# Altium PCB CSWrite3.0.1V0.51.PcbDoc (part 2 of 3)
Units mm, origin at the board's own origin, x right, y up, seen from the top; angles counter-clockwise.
Board outline 100 x 80 mm, 4 copper layers (Top Layer, power, gnd, Bottom Layer), stack 0.778 mm thick; 246 components, 181 nets, 873 pads, 864 vias.
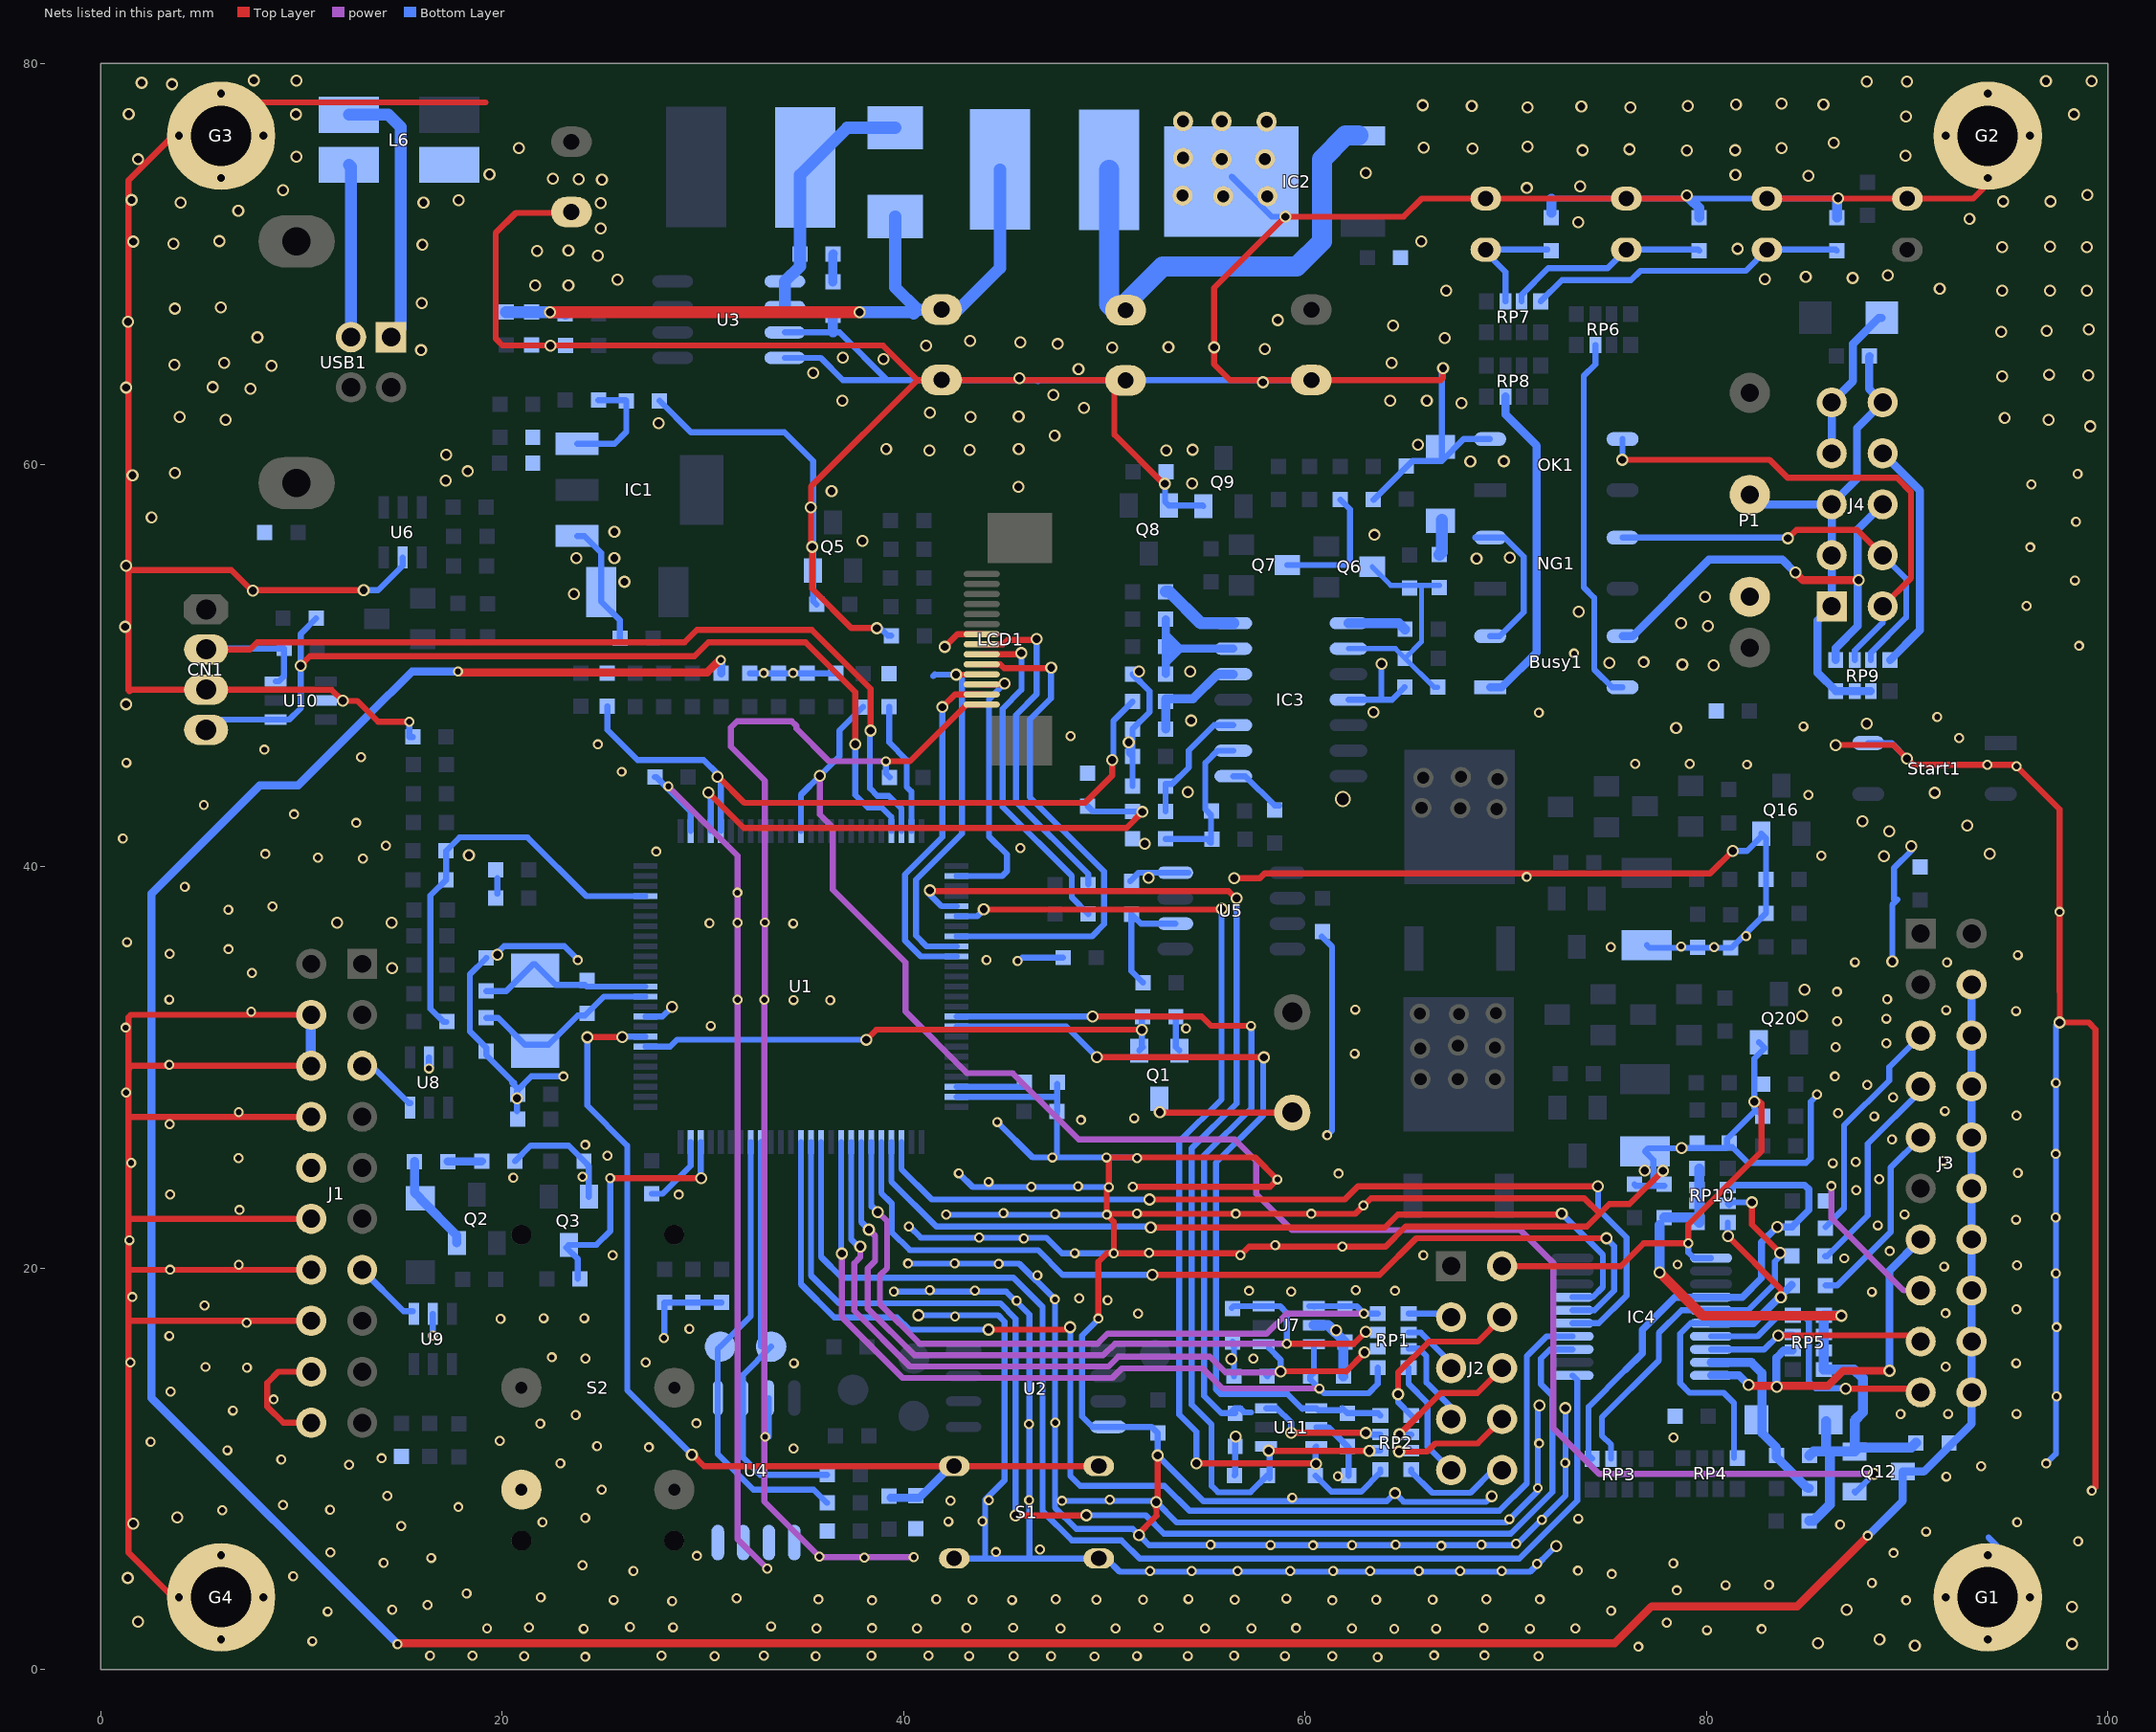
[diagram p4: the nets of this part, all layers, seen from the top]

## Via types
v1: diameter 0.5, hole 0.3, Top Layer to Bottom Layer, 444 vias
v2: diameter 0.6, hole 0.4, Top Layer to Bottom Layer, 412 vias
v3: diameter 0.8, hole 0.6, Top Layer to Bottom Layer, 8 vias

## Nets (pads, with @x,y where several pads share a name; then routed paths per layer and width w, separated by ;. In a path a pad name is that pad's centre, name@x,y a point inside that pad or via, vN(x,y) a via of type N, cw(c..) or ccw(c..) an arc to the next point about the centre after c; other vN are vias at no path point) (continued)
Buzzer: Q1.1 R8.1 U1.7 | length 26.9
  Top Layer w0.3: v2(38.13,31.37) 38.63,31.87 v2(51.87,31.87)
  Bottom Layer w0.3: U1.7@27.137,31.022 28.36,31.022 28.708,31.37 v2(38.13,31.37) v2@38.15,31.37 ; Q1.1@51.734,30.83 51.908,31.005 51.87,31.043 v2(51.87,31.87) 51.87,32.474 R8.1@51.908,32.512
CLK-a: IC4.5 U1.78 | length 46.3
  Top Layer w0.3: v2(52.25,23.41) 61.97,23.41 62.63,24.07 v2(74.59,24.07) 74.59,24.06 v2@74.63,24.02
  Bottom Layer w0.3: U1.78@39.887,26.272 39.887,24.933 41.41,23.41 v2(52.25,23.41) ; IC4.5@73.32,17.245 74.635,17.245 76.01,18.62 76.01,21.52 74.59,22.94 v2(74.59,24.07)
CLK-b: IC4.16 R40.1 RP4.8 RP10.8 | length 19.7
  Top Layer w0.3: v2(81.06,21.59) 83.7,18.95 v2(83.7,18.54)
  Bottom Layer w0.3: IC4.16@80.22,17.245 79.205,17.245 78.68,16.72 78.68,14.26 79.16,13.78 80.86,13.78 81.36,13.28 RP4.8@81.36,10.54 ; RP10.8@81.05,22.265 81.05,21.6 v2(81.06,21.59)
  Bottom Layer w0.4: IC4.16@80.22,17.245 82.325,17.245 R40.1@84.242,19.162
D0: C67.2 RP1.4 U1.81 U7.1 | length 37.7
  power w0.3: v2(38.72,22.78) 39.18,22.32 39.18,20 38.82,19.64 38.82,18.21 40.8,16.23 49.66,16.23 50.16,16.73 58.08,16.73 59.08,17.73 v1(62.93,17.73)
  Bottom Layer w0.3: U1.81@38.387,26.272 38.387,23.063 38.437,23.063 v2(38.72,22.78) ; U7.1@60.215,18.095 U7.1@60.432,18.095 ; U7.1@60.447,18.08 U7.1@60.432,18.095 ; RP1.4@63.619,17.733 62.933,17.733 v1(62.93,17.73) 62.565,18.095 U7.1@60.432,18.095
D1: C70.2 RP1.3 U1.82 U7.6 | length 39.5
  Top Layer w0.3: v1(59.09,16.23) 62.38,16.23 62.41,16.2 v2(63.03,16.82)
  power w0.3: v2(38.27,21.91) 38.58,21.6 38.58,20.35 38.21,19.98 38.21,17.98 40.54,15.65 49.944,15.65 50.524,16.23 v1(59.09,16.23)
  Bottom Layer w0.3: U1.82@37.887,26.272 37.887,22.293 v2(38.27,21.91) ; C70.2@56.35,18.009 56.436,18.095 U7.6@57.932,18.095 58.755,18.095 59.09,17.76 v1(59.09,16.23)
D2: C69.2 RP1.2 U1.83 U7.4 | length 38.8
  Top Layer w0.3: v2(58.78,14.851) 62.039,14.851 62.045,14.845 v2@62.96,15.76
  power w0.3: v2(37.84,21.07) 37.84,20.54 37.537,20.237 37.537,17.873 40.32,15.09 50.2,15.09 50.69,15.58 55.25,15.58 56.038,14.792 58.72,14.792 v2(58.78,14.851)
  Bottom Layer w0.3: U1.83@37.387,26.272 37.387,21.423 37.84,20.97 v2(37.84,21.07) ; C69.2@58.125,14.605 58.05,14.68 58.075,14.705 58.14,14.64 58.352,14.851 v2(58.78,14.851) 58.78,15.428 58.199,16.009 U7.4@58.199,16.075
  other v2: 62.96,15.8
D3: C68.2 RP1.1 U1.84 U7.3 | length 40.9
  power w0.3: v2(36.92,20.72) 36.92,17.55 39.95,14.52 50.38,14.52 50.86,15 54.89,15 55.895,13.995 v1(60.705,13.995)
  Bottom Layer w0.3: U1.84@36.887,26.272 36.887,20.713 36.92,20.68 v2(36.92,20.72) ; U7.3@60.432,16.195 60.432,14.776 C68.2@60.261,14.605 60.261,14.439 v1(60.705,13.995) 60.94,13.76 63.16,13.76 63.619,14.219 RP1.1@63.619,15.033
D4: C71.1 RP2.8 U1.67 U11.1 | length 42.6
  Top Layer w0.3: v2(49.63,30.5) 57.93,30.5 v2(57.94,30.49) 57.98,30.49 v2@58.07,30.58 ; v2@58.067,30.624 v2@58.07,30.58 ; v2@58.07,30.621 v2@58.07,30.58 ; v2@58.07,30.619 v2@58.07,30.58
  Bottom Layer w0.3: U1.67@42.637,32.022 48.108,32.022 v2(49.63,30.5) ; v2@57.855,30.49 57.91,30.435 57.91,27.6 55.56,25.25 55.56,13.946 55.776,13.73 59.12,13.73 59.835,13.015 ; 59.86,12.99 59.835,13.015 ; RP2.8@63.746,12.653 63.636,12.763 C71.1@62.103,12.763 61.852,13.015 61.747,12.91 60.664,12.91 U11.1@60.559,13.015 59.835,13.015
D5: C74.2 RP2.7 U1.66 U11.6 | length 44
  Top Layer w0.3: v2(49.41,32.53) 54.85,32.53 55.32,32.06 v1(57.3,32.06) ; v2(59.3,11.79) 63.01,11.79 v2(63.02,11.78)
  Bottom Layer w0.3: U1.66@42.637,32.522 49.402,32.522 v2(49.41,32.53) ; C74.2@56.515,12.763 C74.2@56.243,12.763 ; 57.31,12.81 56.971,12.81 56.766,13.015 56.495,13.015 C74.2@56.243,12.763 ; v1@57.32,32.06 57.32,27.96 54.97,25.61 54.97,13.625 55.831,12.763 C74.2@56.243,12.763 ; U11.6@58.059,13.015 58.595,13.015 59.3,12.31 v2(59.3,11.79) ; v2(63.02,11.78) 63.097,11.703 RP2.7@63.746,11.703
D6: C73.2 RP2.6 U1.55 U11.4 | length 58.2
  Top Layer w0.3: v2(41.31,38.81) 41.34,38.78 56.19,38.78 56.585,38.385 v2(56.585,38.41) ; v2(58.18,10.9) 58.19,10.89 v2(63.2,10.89)
  Bottom Layer w0.3: v2(41.31,38.81) 41.31,38.64 41.29,38.62 41.888,38.022 U1.55@42.637,38.022 ; v2(56.585,38.41) 56.585,28.195 54.35,25.96 54.35,13.19 55.34,12.2 55.34,9.15 55.66,8.83 57.285,8.83 C73.2@58.125,9.67 ; v2(58.18,10.9) 58.18,10.895 58.229,10.945 C73.2@58.229,9.525 ; v2(63.2,10.89) 63.213,10.903 RP2.6@63.746,10.903
D7: C72.2 RP2.5 U1.56 U11.3 | length 53.1
  Top Layer w0.3: v2(43.99,37.86) v2@55.78,37.86 ; v2(54.59,10.27) 60.52,10.27 v2(60.55,10.24)
  Bottom Layer w0.3: U1.56@42.637,37.522 43.672,37.522 43.99,37.84 v2(43.99,37.86) ; v2(54.59,10.27) 54.59,11.84 53.73,12.7 53.73,26.3 55.84,28.41 v2(55.84,37.9) ; C72.2@60.515,9.652 61.307,8.86 62.8,8.86 63.746,9.806 RP2.5@63.746,9.953 ; v2@60.515,10.24 60.515,11.072 U11.3@60.559,11.115
DA-Vdd: R43.1 R78.2 U1.29 | length 27.5
  Top Layer w0.3: v2(30.28,43.68) 32.04,41.92 51.1,41.92 v2(51.9,42.72)
  Bottom Layer w0.3: v2(30.28,43.68) 30.387,43.573 U1.29@30.387,41.772 ; R78.2@49.17,43.005 49.434,42.741 R43.1@51.401,42.741 51.879,42.741 v2(51.9,42.72)
DA-Vpp: R51.1 R79.2 U1.30 | length 35.2
  Top Layer w0.3: v2(30.72,44.47) 30.77,44.47 32.07,43.17 49.03,43.17 50.39,44.53 v2(50.39,45.3)
  Bottom Layer w0.3: R79.2@25.24,47.984 25.24,46.81 26.74,45.31 30.034,45.31 30.72,44.624 v2(30.72,44.47) 30.754,44.47 30.774,44.45 30.734,44.41 30.887,44.257 U1.30@30.887,41.772 ; v2@50.45,45.5 50.45,47.264 R51.1@51.401,48.215
GND: Busy1.2 Busy.2 C1.1 C2.1 C3.1 C4.2 C5.1 C6.1 C7.1 C8.1 C9.2 C10.2 C11.2 C12.2 C13.1 C14.1 C15.2 C16.2 C17.1 C18.1 C25.1 C27.1 C28.2 C30.2 C32.1 C33.1 C35.1 C36.2 C38.1 C39.2 C40.2 C41.2 C42.2 C43.2 C44.2 C45.2 C46.2 C49.1 C50.1 C51.1 C56.1 C57.2 C58.2 C59.2 C60.1 C61.1 C62.2 C63.2 C64.1 C65.1 C66.1 C67.1 C68.1 C69.1 C70.1 C71.2 C72.1 C73.1 C74.1 C75.2 C76.2 C77.2 CN1.3 DZ1.1 G1.1 G2.1 G3.1 G4.1 IC1.1 IC2.2 IC3.11 IC4.11 J1.4 J1.6 J1.8 J1.10 J1.12 J1.14 J1.16 J1.18 J1.20 J2.2 L2.2 L6.1 L7.1 L11.1 LCD1.1 LCD1.8 NG1.2 NG.2 OK1.2 OK.2 P1.2 pad.21 pad.22 pad.23 pad.24 pad.25 pad.26 pad.27 pad.28 pad.29 POWER.2 Q1.3 Q3.3 Q5.3 Q8.3 Q9.3 Q16.3 Q20.3 R1.1 R8.2 R10.1 R15.2 R22.2 R23.2 R24.2 R35.2 R36.1 R48.1 R52.2 R53.1 R57.1 R59.1 R62.1 R63.2 R64.1 R68.1 R78.1 R79.1 S1.1 S2.1 Start1.4 U1.10 U1.27 U1.74 U1.99 U2.4 U3.7 U3.8 U4.1 U4.2 U4.3 U4.4 U4.7 U5.4 U6.2 U7.2 U8.2 U9.2 U10.2 U11.2 | length 1046.4
  Top Layer w0.3: 1.42,24.99 1.38,24.95 ; 1.44,48.72 1.38,48.78 ; G4.1@3.6,3.6 1.38,5.82 1.38,17.34 ; J1.20@10.49,12.29 9.1,12.29 8.3,13.09 8.3,14.28 8.85,14.83 J1.18@10.49,14.83 ; J1.16@10.49,17.37 1.41,17.37 1.38,17.34 ; J1.14@10.49,19.91 1.44,19.91 1.38,19.97 ; J1.12@10.49,22.45 1.44,22.45 1.38,22.39 ; J1.8@10.49,27.53 1.39,27.53 1.38,27.54 ; J1.6@10.49,30.07 1.56,30.07 1.38,29.89 ; J1.4@10.49,32.61 1.5,32.61 1.38,32.49 1.38,29.89 ; v2(13.1,53.76) 7.52,53.76 6.51,54.77 v2@1.38,54.77 ; v1(15.38,47.21) 13.82,47.21 12.78,48.25 v2(12.06,48.25) 11.5,48.81 CN1.3@5.25,48.81 1.41,48.81 1.38,48.78 ; 19.18,78.06 5.26,78.06 1.38,74.18 v2@1.38,54.77 ; C9.2@22.96,72.56 20.68,72.56 19.68,71.56 19.68,66.3 20.027,65.953 v2(22.41,65.953) 38.97,65.953 40.69,64.233 ; v2@35.383,55.92 35.383,58.926 40.69,64.233 ; v2(35.44,55.92) 35.44,53.83 37.39,51.88 38.71,51.88 38.7,51.87 v2(38.66,51.87) ; v1(39.11,45.24) 40.31,45.24 43.14,48.07 LCD1.1@43.89,48.07 ; v2(42.05,50.94) 42.68,51.57 LCD1.8@43.89,51.57 ; v1(49.7,17.48) 49.7,20.31 50.12,20.73 v1(50.47,20.73) ; v1(51.415,24.05) 58.26,24.05 v1(58.62,24.41) 57.522,25.508 v1(50.11,25.508) 50.11,25.43 50.1,25.42 50.22,25.3 v1(50.22,24.03) 50.22,24.02 50.12,23.92 v1(50.12,22.65) ; v2@51.57,6.62 52.61,7.66 52.59,7.68 v2(52.59,8.34) 52.59,8.15 52.61,8.13 v2@52.56,8.08 ; v2@51.64,6.69 v2(51.73,6.69) ; v2@52.65,8.37 v2(52.65,10.66) ; v2@53.02,58.98 v2(53.02,59.07) 52.936,59.07 50.5,61.506 50.5,64.233 40.69,64.233 ; v2(56.47,39.41) 57.742,39.41 57.982,39.65 80.17,39.65 v2(81.3,40.78) ; v2(66.87,64.82) 66.87,64.346 66.757,64.233 C12.2@60.31,64.233 56.25,64.233 55.46,65.023 55.46,68.82 v2(59.01,72.37) 64.9,72.37 65.8,73.27 Busy.2@69,73.27 NG.2@76,73.27 v2@79.01,73.27 ; J2.2@69.81,20.09 75.72,20.09 76.86,21.23 v1(79.09,21.23) 79.09,22.17 82.73,25.81 82.73,28.2 82.639,28.291 v2(82.38,28.291) ; v2(77.82,24.84) 76.16,23.18 75.15,23.18 74.67,22.7 ; OK.2@83,73.27 POWER.2@90,73.27 93.27,73.27 G2.1@96.4,76.4 ; v2(86.42,46.05) 89.31,46.05 v2(89.98,45.38) 90.3,45.06 95.37,45.06 97.58,42.85 97.58,38.35 ; 97.574,38.356 97.58,38.35 ; v1(99.19,8.9) 99.37,9.08 99.37,31.89 99.03,32.23 v2(97.59,32.23) 97.59,33.75 97.58,33.76 97.58,38.35 ; 1.38,17.34 1.38,19.97 ; 1.38,19.97 1.38,22.39 ; 1.38,22.39 1.38,24.95 ; 1.38,24.95 1.38,27.54 ; 1.38,27.54 1.38,29.89 ; 1.38,48.78 v2@1.38,54.77 ; v1(50.12,22.65) 50.47,22.3 v1(50.47,20.73) ; v1(50.12,22.65) 50.17,22.7 v1(56.55,22.7) v1(60.31,22.7) 62.51,22.7 63.28,23.47 73.9,23.47 74.67,22.7 ; v1(50.47,20.73) 56.69,20.73 v1(56.78,20.64) 57.2,21.06 v1(61.86,21.06) 64.009,21.06 65.009,22.06 74.03,22.06 74.67,22.7
  power w0.3: v1(28.28,43.989) 31.73,40.539 v1(31.73,33.365) 31.73,6.49 v1(33.2,5.02) ; v1(39.11,45.24) 36.292,45.24 34.66,46.872 34.66,47.01 34.43,47.24 31.7,47.24 31.39,46.93 31.39,45.97 33.09,44.27 v1(33.09,37.212) 33.09,33.365 v1(33.06,33.365) 33.06,8.37 v1(35.81,5.62) 35.81,5.59 v1(40.51,5.59)
  Bottom Layer w0.3: v2(13.1,53.76) 13.82,53.76 15.05,54.99 U6.2@15.05,55.39 ; v1(15.38,47.21) 15.38,46.451 L2.2@15.56,46.451 ; v1(16.36,29.94) U8.2@16.36,30.49 ; v1(16.54,16.63) 16.55,16.64 U9.2@16.55,17.72 ; C3.1@19.214,35.444 18.39,34.62 18.39,31.79 19.214,30.966 C1.1@19.214,30.808 19.214,30.606 20.595,29.225 20.495,29.225 20.65,29.07 ; v2(19.757,35.61) 19.757,35.697 20.09,36.03 23.1,36.03 23.77,35.36 v1(23.77,35.33) ; C42.2@19.764,38.64 19.764,39.41 ; C8.1@20.643,25.318 21.415,26.09 23.311,26.09 R10.1@24.077,25.324 24.32,25.081 Q3.3@24.32,23.55 ; 20.733,27.813 v2(20.733,28.447) 20.733,28.823 21.46,29.55 23.04,29.55 v1(23.05,29.54) ; v2(22.41,65.953) R23.2@23.162,65.953 ; IC1.1@23.74,56.46 24.1,56.46 24.94,55.62 C4.2@24.94,53.66 24.94,53.2 25.865,52.275 C6.1@25.865,51.38 ; U1.10@27.137,32.522 27.992,32.522 28.46,32.99 v2(28.46,33.01) ; C44.2@27.451,23.694 27.994,23.694 29.387,25.087 U1.99@29.387,26.272 ; C43.2@27.605,44.457 27.673,44.457 v1@28.141,43.989 ; C56.1@27.835,63.2 29.405,61.63 34.06,61.63 35.488,60.202 v2@35.488,55.872 ; v1(28.05,16.51) 28.086,16.546 R62.1@28.086,18.276 R57.1@29.506,18.276 R1.1@30.927,18.276 ; v1(28.28,43.989) v1@28.141,43.989 ; U1.27@29.387,41.772 29.387,42.743 v1@28.141,43.989 ; C59.2@32.338,49.62 R15.2@33.393,49.62 ; v1(33.1,11.59) 33.285,11.59 U4.7@33.285,13.52 ; R15.2@33.397,49.616 R15.2@33.393,49.62 ; U3.8@34.084,65.335 35.865,65.335 36.967,64.233 39.177,64.233 ; U3.7@34.084,66.605 36.49,66.605 36.805,66.605 39.177,64.233 ; v2(35.44,55.92) v2@35.488,55.872 ; R24.2@35.663,53.055 35.488,53.229 Q5.3@35.488,54.745 v2@35.488,55.872 ; R68.1@36.621,49.62 C57.2@35.193,49.62 R15.2@33.393,49.62 ; v2(38.66,51.87) 38.74,51.87 38.79,51.92 39.215,51.495 C58.2@39.383,51.495 ; v1(39.11,45.24) 39.11,44.634 C40.2@39.304,44.44 ; v1(39.51,18.83) 45.106,18.83 46.26,17.676 46.26,5.59 46.32,5.53 ; v1(40.22,20.22) 45.754,20.22 v1(47.54,18.434) 47.54,8.06 48.6,7 51.42,7 v2(51.73,6.69) ; v1(40.26,22.063) 40.297,22.063 40.85,21.51 47.11,21.51 47.89,20.73 v1(50.47,20.73) ; v2(40.73,17.642) 44.708,17.642 45.03,17.32 45.03,9.42 44.06,8.45 44.06,5.53 ; v1(42.12,22.66) 42.13,22.65 v1(50.12,22.65) ; S1.1@42.52,5.53 44.06,5.53 ; U1.74@42.637,28.522 47.604,28.522 47.645,28.48 ; v1(42.75,24.72) 43.44,24.03 v1(50.22,24.03) ; v1(44.66,27.27) 46.422,25.508 v1@47.468,25.508 ; v1(45.68,35.29) 45.68,35.23 45.91,35.46 C39.2@47.939,35.46 ; 46.694,64.169 46.63,64.233 ; v1(47.41,25.508) v1@47.468,25.508 ; C45.2@47.635,27.8 47.635,25.675 v1@47.468,25.508 ; C45.2@47.644,27.807 47.645,27.808 47.645,28.48 ; C7.1@47.645,29.17 47.645,28.48 ; v1(47.89,8.4) 52.45,8.4 52.5,8.45 52.56,8.39 52.57,8.4 52.58,8.39 52.59,8.4 v2(52.59,8.34) ; v1(49.7,17.48) 49.7,17.44 48.89,16.63 48.89,12.6 49.405,12.085 U2.4@50.187,12.085 52.354,12.085 C61.1@52.66,11.779 52.66,10.67 v2(52.65,10.66) 54.93,8.38 64.07,8.38 v2(64.47,8.78) 64.898,8.352 69.02,8.352 v2(69.3,8.632) ; C18.1@51.286,39.272 51.316,39.302 51.705,39.692 U5.4@53.532,39.692 U5.4@54.181,39.692 ; C25.1@51.4,45.477 C25.1@51.401,45.478 51.21,45.669 v2(51.21,46.181) v2@51.401,45.99 ; R59.1@51.401,49.584 52.25,48.735 52.25,47.696 C32.1@51.401,46.847 C27.1@51.401,44.001 ; v1(51.63,25.47) 51.6,25.44 51.532,25.508 v1(50.11,25.508) v1@47.468,25.508 ; v2@51.853,6.567 52.23,6.19 70.44,6.19 v1(70.51,6.26) 70.575,6.26 72.97,8.655 72.97,13.01 v2(72.96,13.02) ; v2@52.58,8.37 52.59,8.38 v2(52.59,8.34) ; v2(53.02,59.07) 53.02,58.173 Q8.3@53.21,57.983 54.897,57.983 Q9.3@54.93,57.95 ; R8.2@53.559,32.512 53.559,31.004 Q1.3@53.734,30.83 ; IC2.2@56.335,74.37 58.335,72.37 v2(59.01,72.37) ; C70.1@56.388,16.319 56.451,16.256 C69.1@56.451,14.605 ; C73.1@56.474,9.67 56.515,9.711 C74.1@56.515,11.112 56.515,11.585 v2(56.53,11.6) ; C12.2@60.31,64.233 46.63,64.233 ; U11.2@60.559,12.065 61.151,12.065 C71.2@62.103,11.112 62.166,11.049 C72.1@62.166,9.652 ; C17.1@60.83,36.51 61.34,36 61.34,26.85 v1(61.1,26.61) ; IC3.11@62.16,48.31 63.81,48.31 ; C16.2@63.4,58.274 63.414,58.274 65.345,60.205 66.81,60.205 ; v2(63.8,50.1) 63.8,48.32 63.81,48.31 ; C60.1@64.956,48.934 64.333,48.31 63.81,48.31 ; v2(66.87,64.82) 66.81,64.76 66.81,60.205 ; NG1.2@68.47,56.38 NG1.2@69.21,56.38 69.94,56.38 70.89,55.43 70.89,52.67 69.69,51.47 Busy1.2@69.21,51.47 ; OK1.2@69.21,61.29 67.895,61.29 66.81,60.205 ; v2(71.665,13.16) 71.665,13.095 71.59,13.02 v1(71.59,9.04) 71.59,8.88 70.2,7.49 v1(70.17,7.49) 70.17,7.46 70.03,7.32 53.61,7.32 52.58,8.35 52.59,8.36 v2(52.59,8.34) ; 72.26,73.27 NG.2@76,73.27 79.16,73.27 OK.2@83,73.27 v2@86.54,73.27 ; v2(72.5,6.14) 72.5,6.16 71.21,4.87 50.76,4.87 50.1,5.53 S1.1@49.72,5.53 46.32,5.53 ; C28.2@76.4,24.165 76.47,24.095 77.34,24.095 ; C30.2@77.02,36.083 77.159,35.944 81.228,35.944 C33.1@82.959,37.675 82.959,41.391 Q16.3@82.72,41.63 82.72,41.49 82.01,40.78 v2(81.3,40.78) ; L7.1@77.89,24.095 77.34,24.095 ; v2(78.75,25.98) 80.975,25.98 R63.2@81.015,26.02 ; v1(79.09,21.23) 79.09,20.77 79.365,20.495 IC4.11@80.22,20.495 ; Q20.3@82.606,31.245 82.9,30.951 82.38,30.431 v2(82.38,28.291) 82.38,27.97 82.6,27.75 82.472,27.877 81.015,26.42 R63.2@81.015,26.02 ; v1(85.5,28.64) 85.5,28.6 85.19,28.29 85.19,25.47 84.95,25.23 82.07,25.23 81.28,26.02 R63.2@81.015,26.02 ; Start1.4@88.05,46.15 89.21,46.15 v2(89.98,45.38) ; v2(89.25,35.27) 89.25,38.097 89.51,38.356 89.34,38.356 89.34,39.93 90.19,40.78 v2(90.19,41.01) ; G1.1@94,5.7 94.92,5.7 94.04,6.58 ; v1(96.92,10.26) 97.4,10.74 v1(97.4,19.73) 97.4,32.11 97.52,32.23 v2(97.59,32.23) ; 39.177,64.233 46.63,64.233 ; 44.06,5.53 46.32,5.53 ; C27.1@51.4,44 C27.1@51.401,44.001 ; 77.34,24.095 77.35,24.105 77.35,25.38 C36.2@76.93,25.8 77.095,25.965 80.96,25.965 R63.2@81.015,26.02
  Bottom Layer w0.5: J1.6@10.478,30.451 J1.4@10.478,32.991 ; C63.2@36.48,67.465 36.48,66.615 36.49,66.605 ; U7.2@60.432,17.145 61.15,17.145 C67.1@61.976,16.319 61.912,16.256 C68.1@61.912,14.605 ; 72.26,73.27 72.263,73.267 C64.1@72.263,72.581 ; v2(79.01,73.42) 79.16,73.27 79.629,72.801 C65.1@79.629,72.326 ; C66.1@86.487,72.326 v2@86.487,73.217
  other v1: 63.61,0.61 24.14,0.63 49.51,0.65 21.095,0.66 27.94,0.68 30.587,0.66 33.04,0.68 35.62,0.66 38.39,0.68 41.24,0.68 43.26,0.67 45.48,0.66 47.35,0.66 51.62,0.67 54.16,0.67 58.99,0.67 61.35,0.66 71.62,0.66 16.41,0.69 18.52,0.69 56.46,0.69 66.42,0.7 68.93,0.7 76.6,1.13 10.55,1.41 80.02,1.96 64.44,2.02 82.744,2.01 19.25,2.05 24.06,2.03 35.66,2.04 40.66,2.04 47.82,2.05 50.55,2.05 55.01,2.04 57.32,2.05 62.33,2.04 66.521,2.03 71.2,2.03 73.455,2.04 38.42,2.06 43.13,2.07 59.55,2.06 68.88,2.06 21.33,2.09 28.52,2.1 45.46,2.08 52.7,2.08 26.374,2.11 33.4,2.15 78.02,2.33 11.31,2.89 75.24,2.92 14.53,2.98 16.277,3.21 28.47,3.4 38.421,3.44 61.36,3.44 89.94,3.44 25.55,3.46 45.4,3.46 49.61,3.47 56.49,3.47 35.75,3.49 41.63,3.5 43.43,3.48 47.58,3.5 51.927,3.48 63.538,3.48 66.35,3.48 69.03,3.5 71.69,3.49 54.19,3.51 31.68,3.54 59.06,3.53 21.92,3.59 18.23,3.78 78.51,3.94 80.94,4.2 83.105,4.22 88.23,4.31 9.592,4.64 75.276,4.75 26.54,4.9 52.27,4.9 54.34,4.9 56.63,4.9 59.26,4.9 61.39,4.9 63.24,4.9 65.66,4.9 67.72,4.9 69.79,4.9 73.59,4.92 24,5.196 71.55,5.26 78.34,5.29 14.1,5.31 16.464,5.556 38.05,5.57 29.7,5.66 89.31,5.8 11.44,5.83 44.6,5.85 46.79,5.98 66.78,6.16 60.39,6.18 62.34,6.19 58.28,6.2 64.51,6.21 55.29,6.22 68.78,6.22 98.5,6.38 90.93,6.87 14.976,7.14 86.65,7.22 95.47,7.33 22.01,7.34 42.23,7.37 43.92,7.39 71.79,7.45 73.6,7.51 24.14,7.55 6.06,7.93 11.43,7.96 17.82,8.09 9.085,8.19 42.34,8.41 44.24,8.43 46.25,8.43 50.27,8.45 59.36,8.56 14.28,8.65 24.96,8.95 61.63,9.62 91.94,9.61 93.67,10.13 12.38,10.19 22.9,10.271 72.95,10.29 9,10.456 13.99,10.52 6.31,10.92 34.51,11 27.31,11.07 24.73,11.12 71.66,11.26 2.49,11.34 19.887,11.39 78.35,11.552 46.24,12.22 21.9,12.25 29.684,12.26 47.55,12.3 23.66,12.67 89.66,12.72 92.03,12.73 95.44,12.73 6.59,12.9 8.62,13.45 97.43,13.6 3.48,13.84 7.29,15.04 5.23,15.07 91.91,15.08 34.53,15.26 95.42,15.26 1.48,15.29 27.15,15.29 24.15,15.494 57.42,15.49 22.47,15.55 3.42,16.618 29.33,16.96 97.43,17.05 7.27,17.28 19.921,17.47 22.064,17.5 24.09,17.5 42.56,17.58 51.67,17.73 91.9,17.74 95.428,17.94 5.17,18.13 45.63,18.37 50.16,18.4 48.75,18.49 1.57,18.55 88.23,18.81 59.3,18.82 57.209,18.86 64.48,18.86 41.3,18.89 43.55,18.869 62.52,18.89 46.66,19.63 3.46,19.91 91.83,20.071 6.88,20.16 95.46,20.14 78.55,20.171 44.73,20.21 42.54,20.23 86.86,20.48 25.51,20.63 65.89,20.63 48.52,20.74 52.23,20.75 89.12,20.84 58.51,21.14 1.43,21.385 45.99,21.47 43.76,21.52 88.52,22.12 95.41,22.41 97.38,22.52 89.86,22.67 47.545,22.69 51.62,22.72 44.97,22.73 6.92,22.89 62.9,23.12 3.46,23.66 28.8,23.651 87.45,23.87 46.36,24.05 48.69,24.07 44.23,24.29 88.59,24.42 20.557,24.5 24.01,24.548 61.67,24.7 95.5,24.73 1.52,25.24 86.28,25.22 87.43,25.28 91.79,25.34 6.87,25.47 25.25,25.595 97.39,25.68 24.14,26.13 89.23,26.4 3.44,27.16 48.83,27.37 51.49,27.46 88.35,27.555 95.44,27.6 86.55,27.72 6.88,27.76 91.87,27.82 89.29,28.5 1.27,28.74 88,29.124 97.4,29.21 86.39,29.54 3.42,30.12 62.464,30.68 86.43,31 88.96,31.2 54.07,31.93 1.25,31.97 30.387,32.06 86.5,32.29 88.96,32.42 7.5,32.76 95.41,32.8 91.93,32.85 62.5,32.87 36.34,33.34 3.42,33.37 34.52,33.35 88.99,33.39 86.49,33.76 7.53,34.696 91.97,35.22 87.39,35.23 44.13,35.34 95.5,35.59 3.44,35.65 6.37,35.88 80.38,35.98 75.23,35.99 78.73,36.02 1.31,36.23 81.96,36.53 30.33,37.179 34.5,37.16 31.73,37.195 97.58,37.74 6.36,37.85 8.558,38.01 31.72,38.69 4.19,38.99 71.04,39.48 13.06,40.39 10.82,40.44 85.71,40.53 8.2,40.623 27.68,40.74 45.81,40.92 14.21,41.04 1.11,41.4 12.73,42.17 9.63,42.6 5.14,43.07 85.07,43.56 25.95,44.72 95.44,44.99 82.007,45.078 93.98,45.06 76.44,45.11 79.16,45.12 1.28,45.17 12.97,45.44 8.15,45.82 24.77,46.08 92.577,46.4 48.32,46.5 84.82,46.98 91.49,47.45 71.64,47.67 33.03,49.63 34.49,49.63 73.4,50.61 98.55,50.99 95.94,52.98 98.35,54.25 96.12,55.9 98.4,57.18 96.18,59.03 98.48,59.55
  other v2: 90.373,1.194 98.196,1.27 85.54,1.3 88.61,1.5 1.86,2.38 86.97,2.97 98.196,3.124 1.35,4.56 1.63,7.26 3.81,7.57 56.32,15.47 61.535,16.9 76.92,24.845 84.76,32.55 84.88,33.86 14.52,34.94 11.78,37.2 14.5,37.2 52.21,39.44 88.84,40.52 18.342,40.57 94.1,40.63 52.01,41.142 89.09,41.75 92.98,42.03 87.76,42.25 91.37,43.67 54.16,43.7 78.48,46.908 87.98,47.11 54.33,47.27 63.41,47.69 1.27,48.08 51.73,49.72 54.28,49.72 80.34,50.03 78.79,50.06 75.15,50.14 76.86,50.18 1.22,51.94 80.06,51.97 78.72,52.12 73.63,52.7 79.92,53.44 23.57,53.58 7.59,53.75 26.09,54.18 1.27,54.98 68.54,55.33 23.69,55.37 25.59,55.37 70.2,55.39 37.95,56.22 63.45,56.52 25.59,56.67 2.54,57.38 35.37,57.88 36.412,58.69 45.71,58.91 54.37,59.08 17.19,59.23 1.59,59.49 3.7,59.6 18.288,59.69 68.23,60.18 69.9,60.19 17.21,60.51 41.29,60.72 53.09,60.72 43.28,60.74 54.39,60.76 39.13,60.8 45.73,60.8 65.62,61.01 47.52,61.47 99.1,61.93 27.79,62.08 6.22,62.25 97.04,62.25 94.85,62.34 3.94,62.4 43.34,62.39 45.73,62.41 41.31,62.61 48.98,62.84 67.79,63.08 36.95,63.2 64.24,63.21 66.06,63.2 47.45,63.48 7.46,63.79 1.27,63.86 5.588,63.881 57.89,64.12 45.76,64.33 94.72,64.42 99.01,64.46 97.06,64.5 35.5,64.59 48.71,64.77 8.52,64.941 3.67,64.99 6.16,65.08 64.31,65.08 39,65.28 36.97,65.34 15.96,65.72 57.985,65.77 50.39,65.85 53.19,65.87 55.46,65.86 41.11,65.94 47.67,66.03 45.81,66.12 43.32,66.19 66.95,66.32 7.81,66.36 94.68,66.64 96.94,66.68 99.04,66.76 64.38,66.95 1.36,67.13 58.63,67.22 3.7,67.79 5.98,67.85 16,68.06 67.03,68.69 94.73,68.69 97.1,68.69 98.94,68.69 91.61,68.78 21.65,68.95 23.3,68.94 25.75,69.24 82.906,69.266 87.274,69.317 84.938,69.367 89.02,69.44 24.77,70.43 21.74,70.67 23.3,70.68 81.55,70.77 94.73,70.85 98.94,70.85 97.1,70.88 16.03,70.97 3.63,71.02 1.63,71.13 65.79,71.14 5.92,71.15 24.92,71.78 73.61,72.09 93.091,72.263 6.858,72.669 3.98,73.07 24.92,73.05 16.08,73.08 94.76,73.13 97.12,73.13 17.84,73.19 1.54,73.2 86.54,73.28 98.97,73.45 9.093,73.685 71.04,73.8 73.7,73.88 24.97,74.21 22.52,74.26 23.81,74.24 85.065,74.397 81.432,74.447 19.37,74.48 63.02,74.55 1.87,75.23 9.754,75.362 89.91,75.41 79.02,75.66 73.81,75.68 81.42,75.68 76.15,75.73 68.33,75.76 20.84,75.78 83.74,75.78 65.91,75.82 71.08,75.86 86.33,76.05 89.94,77.37 1.4,77.48 9.728,77.47 98.298,77.47 71.07,77.81 76.21,77.81 73.76,77.86 68.3,77.89 79.06,77.89 65.85,77.92 81.46,77.95 85.82,77.95 83.74,78.01 3.556,78.969 2.04,79.04 87.98,79.1 89.97,79.1 9.75,79.14 96.901,79.121 99.187,79.121 7.64,79.16
  other v3: 61.88,43.36
GND1: C29.2 DZ2.1 L7.2 Q12.3 R75.2 R76.1 RP5.1 RP5.2 RP5.3 RP5.4 RP10.1 RP10.2 RP10.3 RP10.4 | length 37.5
  Top Layer w0.5: v2(77.65,19.77) 79.8,17.62 v2(86.71,17.62)
  Bottom Layer w0.5: v2(77.65,19.77) L7.2@77.65,22.144 ; L7.2@77.89,22.515 79.375,22.515 79.63,22.26 RP10.4@79.63,24.96 ; R75.2@85.105,7.4 85.33,7.4 86.14,8.21 86.14,10.75 86.03,10.86 ; C29.2@85.125,10.66 85.325,10.86 86.03,10.86 ; DZ2.1@85.948,12.36 85.948,10.942 86.03,10.86 ; v2(86.71,17.62) 86.688,17.642 RP5.1@85.836,17.642 RP5.2@85.836,16.692 RP5.3@85.836,15.892 RP5.4@85.836,14.942 87.338,14.942 87.78,14.5 87.78,12.81 87.37,12.4 Q12.3@87.37,10.86 ; R76.1@90.425,11.29 90.194,11.06 87.57,11.06 Q12.3@87.37,10.86 ; 86.03,10.86 Q12.3@87.37,10.86
GND2: C34.1 J4.1 J4.3 J4.5 J4.10 P1.3 RP9.2 RP9.3 RP9.4 | length 24.7
  Bottom Layer w0.4: P1.3@82.15,58.516 82.626,58.04 J4.5@86.23,58.04 ; C34.1@88.116,65.43 88.09,65.404 88.09,63.8 J4.10@88.77,63.12 87.49,61.84 87.49,59.3 J4.5@86.23,58.04 ; RP9.2@88.18,48.74 RP9.3@87.38,48.74 RP9.4@86.43,48.74 85.53,49.64 85.53,52.26 J4.1@86.23,52.96 J4.3@86.23,55.5 J4.5@86.23,58.04
GndControl: Q12.1 R77.2 U1.38 | length 85.9
  power w0.3: v2(35.82,44.51) 35.82,42.58 36.47,41.93 36.47,38.84 40.09,35.22 40.09,32.78 43.17,29.7 45.43,29.7 48.72,26.41 56.49,26.41 57.56,25.34 57.56,23.68 59.355,21.885 70.715,21.885 72.36,20.24 72.36,12.02 74.64,9.74 v2(88.33,9.74)
  Bottom Layer w0.3: U1.38@34.887,41.772 34.887,43.577 v2(35.82,44.51) 36.81,45.5 36.81,46.774 R77.2@37.981,47.944 ; Q12.1@87.37,8.86 87.41,8.82 v2(88.33,9.74)
I2C1-DAT: R70.2 T12.1 U1.93 U4.5 | length 22.7
  Bottom Layer w0.3: U1.93@32.387,26.272 32.387,17.608 T12.1@30.861,16.082 30.734,15.955 30.734,10.746 32.517,8.963 35.523,8.963 R70.2@36.188,8.299
I2C1-SCL: R69.2 T11.1 U1.92 U4.6 | length 20.8
  Bottom Layer w0.3: T11.1@32.887,16.09 U1.92@32.887,26.272 ; T11.1@33.4,16.08 32.004,14.684 32.004,10.546 32.854,9.696 R69.2@36.188,9.696
I2C2-DAT: CN1.2 R25.1 U1.48 U10.6 | length 47.8
  Top Layer w0.3: CN1.2@5.25,50.81 7.44,50.81 7.8,51.17 29.09,51.17 29.7,51.78 35.43,51.78 38.35,48.86 v2(38.35,46.77)
  Bottom Layer w0.3: CN1.2@6,50.81 6.05,50.86 R25.1@9.135,50.86 9.135,49.485 8.87,49.22 U10.6@8.72,49.22 ; v2(38.35,46.77) 38.32,46.74 38.32,43.89 38.69,43.52 39.26,43.52 39.887,42.893 U1.48@39.887,41.772
I2C2-SCL: CN1.4 R26.1 U1.47 U10.4 | length 47.6
  Top Layer w0.3: v2(9.96,50.005) 10.425,50.47 29.58,50.47 30.27,51.16 35.12,51.16 37.59,48.69 v2(37.59,46.09)
  Bottom Layer w0.3: CN1.4@4.97,46.53 CN1.4@5.25,46.81 5.76,47.32 U10.4@8.72,47.32 9.4,47.32 9.94,47.86 9.93,47.87 9.96,47.9 v2(9.96,50.005) 9.96,51.585 R26.1@10.736,52.36 ; v2(37.59,46.09) 37.59,43.568 38.208,42.95 38.9,42.95 39.387,42.463 U1.47@39.387,41.772
IO1-a: IC4.1 U1.86 | length 63.1
  Bottom Layer w0.3: U1.86@35.887,26.272 35.887,20.553 36.92,19.52 45.47,19.52 46.92,18.07 46.92,7.89 48.38,6.43 50.85,6.43 51.76,5.52 70.67,5.52 73.56,8.41 73.56,14.405 IC4.1@73.32,14.645
IO1-b: IC4.20 J3.13 RP5.6 | length 19
  Top Layer w0.4: v2(82.08,14.18) 82.14,14.12 86.04,14.12 86.8,14.88 v2(89.11,14.88)
  Bottom Layer w0.4: IC4.20@80.22,14.645 81.615,14.645 v2(82.08,14.18) ; v2(83.49,14.08) 83.48,14.09 83.48,15.53 83.842,15.892 RP5.6@84.296,15.892 ; v2(89.11,14.88) 89.11,19.87 J3.13@90.66,21.42
IO2-a: IC4.3 U1.87 | length 64.3
  Top Layer w0.3: v2(45.57,7.67) 49.01,7.67 49.1,7.58 v2(49.1,7.68)
  Bottom Layer w0.3: U1.87@35.387,26.272 35.387,19.623 36.768,18.242 44.808,18.242 45.58,17.47 45.57,17.46 v2(45.57,7.67) ; v2(49.1,7.68) 52.06,7.68 52.97,6.77 70.242,6.77 70.282,6.81 70.298,6.81 72.32,8.832 72.32,13.64 71.75,14.21 71.75,15.49 72.205,15.945 IC4.3@73.32,15.945
IO2-b: IC4.18 J3.17 RP5.7 | length 11.6
  Top Layer w0.3: v2(83.56,16.64) 90.36,16.64 J3.17@90.66,16.34
  Bottom Layer w0.3: IC4.18@80.22,15.945 82.865,15.945 v2(83.56,16.64) 83.612,16.692 RP5.7@84.296,16.692
IO3-a: IC4.4 U1.88 | length 62
  Top Layer w0.3: v2(44.23,16.93) 48.05,16.93 48.14,17.02 48.15,17.01 48.19,17.05 v2(48.3,17.05)
  Bottom Layer w0.3: U1.88@34.887,26.272 34.887,19.193 36.54,17.54 39.67,17.54 40.28,16.93 v2(44.23,16.93) ; v2(48.3,17.05) 48.3,9.64 48.79,9.15 52.99,9.15 54.238,7.902 69.681,7.902 71.04,9.261 71.04,15.6 72.035,16.595 IC4.4@73.32,16.595
IO3-b: IC4.17 J3.19 RP5.8 | length 14.4
  Top Layer w0.3: v2(86.92,13.98) 90.4,13.98 90.62,13.76 J3.19@90.66,13.8
  Bottom Layer w0.3: IC4.17@80.22,16.595 82.535,16.595 83.582,17.642 RP5.8@84.296,17.642 84.808,17.642 85.09,17.36 85.09,14.34 85.42,14.01 86.97,14.01 87,13.98 v2(86.92,13.98)
KeyMode: C15.1 R71.1 S1.2 U1.8 | length 50.2
  Top Layer w0.3: v2(24.24,31.49) 24.25,31.5 v2(25.99,31.5) ; v2@29.45,10.74 30.06,10.13 S1.2@42.52,10.13 S1.2@49.72,10.13
  Bottom Layer w0.3: v2(24.24,31.49) 24.24,28.09 26.23,26.1 26.23,13.91 v2(29.45,10.69) ; v2(25.99,31.5) 26.012,31.522 U1.8@27.137,31.522
  Bottom Layer w0.4: R71.1@39.34,8.546 40.78,8.546 42.365,10.13 S1.2@42.52,10.13
LCD-CS: LCD1.5 U1.58 | length 27.4
  Top Layer w0.3: LCD1.5@43.89,50.07 44.81,50.07 45,49.88 v2@47.35,49.88 ; v2(47.35,49.9) v2@47.36,49.89
  Bottom Layer w0.3: U1.58@42.637,36.522 49.382,36.522 49.99,37.13 49.99,39.752 46.29,43.452 46.29,47.326 47.34,48.376 ; 47.34,48.376 47.35,48.386 v2(47.35,49.9) 47.34,49.9 47.34,48.376
LCD-DCX: LCD1.4 U1.59 | length 18.8
  Top Layer w0.3: v2(42.61,49.56) 43.88,49.56 LCD1.4@43.89,49.57
  Bottom Layer w0.3: 41.47,49.49 41.55,49.57 41.56,49.56 v2(42.61,49.56) ; U1.59@42.637,36.022 41.148,36.022 40.62,36.55 40.62,39.35 42.9,41.63 42.9,49.33 42.705,49.525 v2@42.705,49.635
LCD-RESET: LCD1.2 U1.60 | length 17.5
  Top Layer w0.3: v2(41.93,47.94) 42.56,48.57 LCD1.2@43.89,48.57
  Bottom Layer w0.3: v2(41.93,47.94) 41.93,41.46 40.07,39.6 40.07,36.305 40.853,35.522 U1.60@42.637,35.522
LCD-SCK: LCD1.3 U1.52 | length 14.1
  Top Layer w0.3: LCD1.3@43.89,49.07 45.18,49.07 45.14,49.11 v2(45.03,49.11)
  Bottom Layer w0.3: U1.52@42.637,39.522 44.902,39.522 45.14,39.76 45.14,40.6 44.25,41.49 44.25,48.33 v2(45.03,49.11)
LCD-SDI: LCD1.6 R54.1 | length 16.8
  Top Layer w0.3: LCD1.6@43.89,50.57 45.55,50.57
  Bottom Layer w0.3: v2(45.87,50.63) 45.87,48.8 44.93,47.86 44.93,42.975 48.38,39.525 48.38,38.451 R54.1@49.196,37.635
LCD-SDO: LCD1.7 R65.1 | length 17
  Top Layer w0.3: LCD1.7@43.89,51.07 44.95,51.07 45.17,51.29 v2@46.63,51.29
  Bottom Layer w0.3: v2(46.63,51.34) 46.63,48.58 45.6,47.55 45.6,43.22 49.196,39.624 R65.1@49.196,39.1
LowPower: Q3.2 R2.1 U1.98 | length 13.1
  Top Layer w0.3: v1(25.38,24.47) v2(29.91,24.47)
  Bottom Layer w0.3: Q3.2@23.193,21.023 23.76,20.456 R2.1@23.76,19.47 ; Q3.2@23.32,21.15 24.7,21.15 25.39,21.84 25.39,24.48 v1(25.38,24.47) ; U1.98@29.887,26.272 29.887,24.493 v2(29.91,24.47)
MISO-a: IC4.7 U1.79 | length 43
  Top Layer w0.3: v2(52.31,22.02) 63.98,22.02 64.62,22.66 v2@72.95,22.66
  Bottom Layer w0.3: U1.79@39.387,26.272 39.387,24.315 41.631,22.07 52.26,22.07 v2(52.31,22.02) ; v2(72.78,22.7) 74.83,20.65 74.83,19.05 74.325,18.545 IC4.7@73.32,18.545
MISO-b: IC4.14 R38.1 RP3.5 RP10.6 | length 24.9
  Bottom Layer w0.3: RP3.5@74.29,10.5 74.12,10.67 74.12,13.08 75.97,14.93
  Bottom Layer w0.35: 75.97,14.93 76.79,15.75 76.79,16.92 78.415,18.545 IC4.14@80.22,18.545 81.785,18.545 82.74,19.5 82.74,21.272 v2(83.51,22.042) 84.271,22.042 84.271,22.066 85.095,22.89 85.095,23.92 84.885,24.13 81.365,24.13 81.25,24.015 81.12,24.015 RP10.6@81.05,24.015
  Bottom Layer w0.4: RP10.6@81.05,24.015 81.085,23.98 81.12,24.015 81.185,24.08 81.25,24.015 RP10.6@81.265,24
MOSI-a: IC4.6 U1.80 | length 47.2
  Top Layer w0.3: v2(52.4,19.66) 63.715,19.66 65.535,21.48 v2(75.001,21.48)
  Bottom Layer w0.3: U1.80@38.887,26.272 38.887,23.743 39.41,23.22 39.41,21.78 40.3,20.89 46.689,20.89 47.919,19.66 v2(52.4,19.66) ; IC4.6@73.32,17.895 74.415,17.895 75.39,18.87 75.39,21.091 v2(75.001,21.48)
MOSI-b: IC4.15 R39.1 RP3.6 RP10.7 | length 20.5
  Top Layer w0.3: v2(82.26,23.27) 82.26,22.16 v2(83.66,20.76)
  Bottom Layer w0.3: RP3.6@75.24,10.5 75.24,11.195 74.78,11.655 74.78,12.56 77.62,15.4 77.62,16.765 78.75,17.895 IC4.15@80.22,17.895 82.075,17.895 83.4,19.22 83.4,20.32 83.66,20.58 v2(83.66,20.76) ; RP10.7@81.05,23.215 81.125,23.14 81.265,23.28 81.275,23.27 v2(82.26,23.27)
NetBusy1_1: Busy1.1 RP8.7 | length 16.4
  Bottom Layer w0.4: Busy1.1@69.21,48.93 69.8,48.93 71.53,50.66 71.53,60.97 69.98,62.52 RP8.7@69.98,63.41
NetBusy1_3: Busy1.3 J4.6 RP9.5 | length 22.5
  Top Layer w0.4: v2(84.42,54.64) 84.8,54.26 v2(87.58,54.26)
  Bottom Layer w0.4: Busy1.3@75.81,51.47 76.3,51.47 80.12,55.29 83.77,55.29 v2(84.42,54.64) ; RP9.5@86.43,50.28 86.43,50.88 87.53,51.98 87.53,56.8 J4.6@88.77,58.04
NetBusy1_4: Busy1.4 RP6.7 | length 18.4
  Bottom Layer w0.3: RP6.7@74.46,65.98 74.46,65.02 73.88,64.44 73.88,53.9 74.4,53.38 74.4,49.82 75.29,48.93 Busy1.4@75.81,48.93
NetBusy_1: Busy.1 C64.2 RP7.6 | length 6.1
  Bottom Layer w0.3: Busy.1@68.86,70.73 69.98,69.61 RP7.6@69.98,68.15 ; Busy.1@69,70.73 C64.2@72.063,70.73
NetBZ1_2: BZ1.2 Q1.2 | length 6.6
  Top Layer w0.3: v2(52.76,27.77) 52.79,27.74 59.04,27.74 BZ1.2@59.29,27.99
NetC1_2: C1.2 R3.2 U1.12 X1.2 | length 9.5
  Bottom Layer w0.3: C1.2@19.214,32.459 19.801,32.459 21.134,31.126 22.306,31.126 23.76,32.58 24.13,32.58 25.072,33.522 U1.12@27.137,33.522
NetC3_2: C3.2 R3.1 U1.13 X1.1 | length 8.9
  Bottom Layer w0.3: C3.2@19.214,33.793 20.203,33.793 21.536,35.126 21.65,35.126 22.677,34.099 24.13,34.099 24.208,34.022 U1.13@27.137,34.022
NetC5_2: C5.2 U1.49 | length 6.7
  Bottom Layer w0.3: C5.2@39.279,47.965 39.279,46.181 40.15,45.31 40.15,43.97 40.387,43.733 U1.49@40.387,41.772
NetC7_2: C7.2 U1.73 | length 3.4
  Bottom Layer w0.3: U1.73@42.637,29.022 45.979,29.022 C7.2@45.993,29.036
NetC8_2: C8.2 R5.1 | length 1.7
  Bottom Layer w0.4: R5.1@17.286,25.3 18.974,25.3 C8.2@18.992,25.318
NetC10_1: C10.1 C13.2 D2.2 L5.1 R14.1 R20.1 | length 36.4
  Top Layer w0.6: v2(22.39,67.62) 22.41,67.6 22.42,67.61 v2(37.8,67.61)
  Bottom Layer w0.6: R14.1@20.193,67.62 v2(22.39,67.62) 23.054,67.62 R20.1@23.142,67.533 ; v2(37.8,67.61) 40.407,67.61 40.427,67.59 40.437,67.6 40.497,67.54 40.69,67.733 ; D2.2@39.58,72.38 39.58,68.843 40.69,67.733 ; L5.1@44.802,74.723 44.802,69.812 42.723,67.733 40.69,67.733
NetC11_1: C11.1 IC2.1 L5.2 | length 25.2
  Bottom Layer w1: L5.2@50.238,74.698 50.238,67.995 50.5,67.733 50.763,67.733 52.91,69.88 59.57,69.88 60.83,71.14 60.83,75.23 62.01,76.41 IC2.1@62.645,76.41
NetC18_2: C18.2 R27.1 U5.2 | length 6
  Bottom Layer w0.3: R27.1@51.925,34.22 51.346,34.799 C18.2@51.346,37.621 51.815,37.152 U5.2@53.532,37.152
NetC27_2: C27.2 IC3.3 R43.2 | length 6.4
  Bottom Layer w0.3: R43.2@53.052,42.741 53.052,44.109 53.379,44.109 54.2,44.93 54.2,45.78 55.46,47.04 IC3.3@56.42,47.04
NetC29_1: C29.1 DZ2.2 IC4.19 R37.2 | length 9.5
  Bottom Layer w0.45: IC4.19@80.22,15.295 82.225,15.295 82.755,14.765 82.755,11.779 83.474,11.06 C29.1@83.474,10.66 83.474,10.586 85.04,9.02 R37.2@85.125,9.02
NetC31_1: C31.1 IC3.2 R46.1 R48.2 | length 8.1
  Bottom Layer w0.3: R48.2@53.052,41.372 55.107,41.372 55.313,41.166 55.313,42.566 55.03,42.849 55.03,45.16 55.64,45.77 IC3.2@56.42,45.77
NetC32_2: C32.2 IC3.5 R51.2 | length 5.4
  Bottom Layer w0.45: C32.2@53.052,46.847 53.052,48.36 54.42,48.36 55.64,49.58 IC3.5@56.42,49.58
NetC37_1: C37.1 IC3.6 R56.1 R59.2 | length 8.2
  Bottom Layer w0.4: R59.2@53.052,49.584 53.052,50.132 ; R56.1@53.052,52.321 53.052,51.568 ; IC3.6@56.42,50.85 53.77,50.85 ; 53.052,50.132 C37.1@53.052,50.953 ; 53.052,50.132 53.77,50.85 ; C37.1@53.052,50.953 53.155,50.85 53.77,50.85 ; C37.1@53.052,50.953 53.052,51.568 ; 53.052,51.568 53.77,50.85
NetC47_1: C47.1 C48.1 L1.2 U1.22 | length 20.7
  Bottom Layer w0.3: L1.2@17.209,32.258 17.082,32.258 16.43,32.91 16.43,38.554 C47.1@17.208,39.332 C48.1@17.208,40.776 17.882,41.45 21.27,41.45 24.198,38.522 U1.22@27.137,38.522
NetC56_2: C56.2 IC1.3 L3.2 | length 5.6
  Bottom Layer w0.3: IC1.3@23.74,61.06 25.6,61.06 26.184,61.644 C56.2@26.184,63.2 26.155,63.23 L3.2@24.796,63.23
NetC60_2: C60.2 IC3.9 Q6.2 R29.1 R32.1 R33.1 | length 13
  Bottom Layer w0.254: IC3.9@62.16,50.85 64.5,50.85 R29.1@64.976,50.374 ; Q6.2@63.343,54.93 64.269,54.004 65.78,54.004 ; C60.2@66.607,48.934 66.416,48.934 R29.1@64.976,50.374 ; R32.1@66.69,54.004 65.78,54.004 ; R29.1@64.976,50.374 65.8,51.197 65.8,53.984 65.78,54.004
NetC63_1: C63.1 R74.1 | length 1.4
  Bottom Layer w0.45: C63.1@36.48,69.116 36.48,70.505 R74.1@36.485,70.51
NetC65_2: C65.2 NG.1 RP7.7 | length 10.1
  Bottom Layer w0.3: RP7.7@70.78,68.15 70.78,68.47 72.11,69.8 75.07,69.8 NG.1@76,70.73 79.575,70.73 C65.2@79.629,70.675
NetC66_2: C66.2 OK.1 RP7.8 | length 15.8
  Bottom Layer w0.3: RP7.8@71.73,68.15 72.79,69.21 76.23,69.21 76.69,69.67 81.94,69.67 OK.1@83,70.73 86.433,70.73 C66.2@86.487,70.675
NetD1_2: D1.2 Q2.3 R5.2 | length 4.9
  Bottom Layer w0.45: R5.2@15.635,25.3 15.635,23.768 D1.2@15.93,23.472 15.93,23.44 17.74,21.63 Q2.3@17.74,21.25
NetD2_1: D2.1 L4.2 R74.2 U3.5 U3.6 | length 12.6
  Bottom Layer w0.6: U3.6@34.084,67.875 U3.5@34.084,69.145 34.838,69.899 34.838,74.447 37.19,76.8 D2.1@39.58,76.8
NetDZ1_2: DZ1.2 R32.2 | length 1.8
  Bottom Layer w0.6: R32.2@66.69,55.535 66.81,55.655 DZ1.2@66.81,57.255
NetIC3_1: IC3.1 R42.1 | length 2.9
  Bottom Layer w0.3: IC3.1@56.42,44.5 57.02,44.5 58.49,43.03 R42.1@58.715,43.03
NetIC3_7: IC3.7 R50.1 | length 4
  Bottom Layer w0.6: R50.1@53.052,53.69 53.23,53.69 54.8,52.12 IC3.7@56.42,52.12
NetIC3_8: IC3.8 R28.1 | length 2.9
  Bottom Layer w0.5: IC3.8@62.16,52.12 64.67,52.12 R28.1@64.976,51.814
NetJ1_5: J1.5 U8.6 | length 3.2
  Bottom Layer w0.3: J1.5@13.03,30.07 13.49,30.07 15.346,28.214 U8.6@15.433,28.214
NetJ1_13: J1.13 U9.1 | length 3.4
  Bottom Layer w0.3: J1.13@13.03,19.91 15.095,17.845 U9.1@15.56,17.845
NetJ2_3: J2.3 RP1.5 | length 2.2
  Bottom Layer w0.3: RP1.5@65.159,17.733 67.087,17.733 J2.3@67.27,17.55
NetJ2_4: J2.4 RP2.1 | length 8.7
  Top Layer w0.3: v2(64.63,13.71) 64.63,14.79 66.17,16.33 68.59,16.33 J2.4@69.81,17.55
  Bottom Layer w0.3: v2(64.63,13.71) 64.63,13.309 RP2.1@65.286,12.653
NetJ2_5: J2.5 RP1.6 | length 3
  Bottom Layer w0.3: RP1.6@65.159,16.783 65.767,16.783 67.27,15.28 J2.5@67.27,15.01
NetJ2_6: J2.6 RP2.2 | length 7.1
  Top Layer w0.3: v2(64.7,11.71) 66.76,13.77 68.57,13.77 J2.6@69.81,15.01
  Bottom Layer w0.3: v2(64.7,11.71) 64.707,11.703 RP2.2@65.286,11.703
NetJ2_7: J2.7 RP1.7 | length 4.7
  Bottom Layer w0.3: RP1.7@65.159,15.983 65.667,15.983 66.04,15.61 66.04,14.3 67.27,13.07 J2.7@67.27,12.47
NetJ2_8: J2.8 RP2.3 | length 6.4
  Top Layer w0.3: v2(64.68,10.85) 66.08,10.85 66.49,11.26 68.6,11.26 J2.8@69.81,12.47
  Bottom Layer w0.3: v2(64.68,10.85) 64.68,10.876 64.707,10.903 RP2.3@65.286,10.903
NetJ2_9: J2.9 RP1.8 | length 6
  Bottom Layer w0.3: RP1.8@65.159,15.033 65.159,14.211 66.1,13.27 66.1,11.1 J2.9@67.27,9.93
NetJ2_10: J2.10 RP2.4 | length 5.5
  Bottom Layer w0.3: RP2.4@65.286,9.953 65.286,9.844 66.328,8.802 68.232,8.802 69.36,9.93 J2.10@69.81,9.93
NetJ3_4: J3.4 J3.6 J3.8 J3.10 J3.12 J3.14 J3.16 J3.18 J3.20 Q12.2 R44.2 R76.2 | length 182.2
  Top Layer w0.4: v1(14.79,1.26) 14.84,1.31 75.43,1.31 77.27,3.15 84.52,3.15 v1(88.03,6.66) ; v1@17.95,49.67 30.22,49.67 30.87,50.32 v1(30.9,50.29)
  Bottom Layer w0.4: 13.299,47.499 15.51,49.71 v1(17.8,49.71) ; 13.495,47.695 9.84,44.04 7.92,44.04 2.53,38.65 2.53,13.52 v1(14.79,1.26) ; v1(30.9,50.29) 30.91,50.28 R44.2@30.91,49.62 ; v1(88.03,6.66) 89.77,8.4 Q12.2@89.77,9.86 90.82,9.86 93.2,12.24 J3.20@93.2,13.8 J3.18@93.2,16.34 J3.16@93.2,18.88 J3.14@93.2,21.42 J3.12@93.2,23.96 J3.10@93.2,26.5 J3.8@93.2,29.04 J3.6@93.2,31.58 J3.4@93.2,34.12
NetJ3_5: J3.5 R38.2 | length 11.5
  Bottom Layer w0.3: R38.2@85.922,22.042 86.84,22.96 86.84,27.09 89.09,29.34 89.09,30.01 J3.5@90.66,31.58
NetJ3_7: J3.7 R39.2 | length 10.5
  Bottom Layer w0.3: R39.2@85.902,20.592 85.992,20.592 88.02,22.62 88.02,26.184 90.66,28.824 J3.7@90.66,29.04
NetJ3_9: J3.9 R40.2 | length 9.7
  Bottom Layer w0.3: R40.2@85.922,19.132 86.512,19.132 89.17,21.79 89.17,25.01 J3.9@90.66,26.5
NetJ3_15: J3.15 R41.2 | length 7.5
  power w0.3: v1(86.21,24.08) 86.21,22.49 89.82,18.88 J3.15@90.66,18.88
NetJ4_2: J4.2 OK1.3 RP9.6 | length 25.6
  Top Layer w0.3: v2(75.8,60.26) 83.13,60.26 84.03,59.36 89.48,59.36 90.18,58.66 90.18,54.37 J4.2@88.77,52.96
  Bottom Layer w0.3: v2(75.8,60.26) 75.81,60.27 OK1.3@75.81,61.29 ; RP9.6@87.38,50.28 87.38,50.76 88.77,52.15 J4.2@88.77,52.96
NetJ4_4: J4.4 NG1.3 RP9.7 | length 20.1
  Top Layer w0.3: v2(84.05,56.35) 84.47,56.77 87.5,56.77 J4.4@88.77,55.5
  Bottom Layer w0.3: NG1.3@75.81,56.38 v2@84.05,56.38 ; RP9.7@88.18,50.28 88.18,50.64 89.94,52.4 89.94,54.33 J4.4@88.77,55.5
NetJ4_7: J4.7 J4.9 R61.1 | length 7.9
  Bottom Layer w0.4: J4.7@86.23,60.58 J4.9@86.23,63.12 87.29,64.18 87.29,66.04 88.58,67.33 R61.1@88.721,67.33
NetJ4_8: J4.8 RP9.8 | length 11.7
  Bottom Layer w0.4: J4.8@88.77,60.58 90.62,58.73 90.62,51.77 RP9.8@89.13,50.28
NetL6_3: L6.3 USB1.1 | length 13.5
  Bottom Layer w0.6: L6.3@12.37,77.45 14.33,77.45 14.94,76.84 14.94,66.84 USB1.1@14.47,66.37
NetL6_4: L6.4 USB1.4 | length 8.6
  Bottom Layer w0.6: L6.4@12.37,74.95 12.47,74.85 USB1.4@12.47,66.37
NetL8_1: L8.1 Q7.2 | length 6.5
  Bottom Layer w0.3: Q7.2@59.113,55.02 62.02,55.02 62.24,55.24 62.24,57.789 L8.1@61.755,58.274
